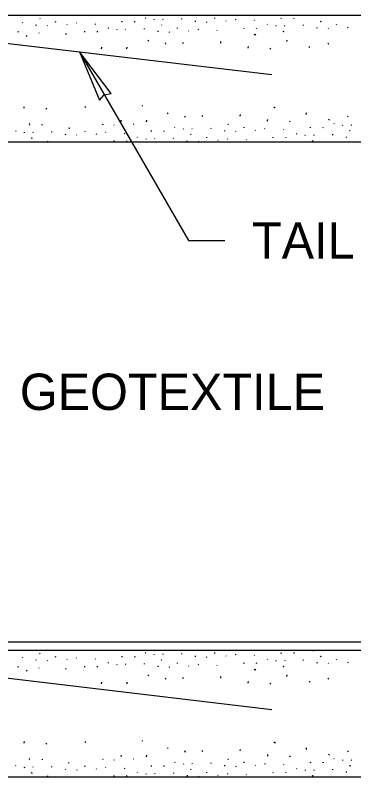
# Model space of a CAD drawing. Extents: x 99862 to 103151, y 100000 to 111076.
# Drawn here: x 100276.5 to 100425.5, y 110543.7 to 110878.5 of the extents above; entities that cross this region are included whole.
import ezdxf

# ---------------------------------------------------------------- set-up
doc = ezdxf.new("R2010")
doc.units = 0
for name, color, linetype in [('Level 11', 7, 'Continuous'), ('Level 15', 7, 'Continuous'), ('Level 18', 7, 'Continuous'), ('Level 20', 7, 'Continuous'), ('Level 24', 7, 'Continuous')]:
    doc.layers.add(name, color=color, linetype=linetype)

msp = doc.modelspace()

# ---------------------------------------------------------------- linework, layer by layer
at = {"layer": 'Level 11'}
for p, q in [((100165.98, 110878.54), (100724.21, 110878.54)), ((100165.98, 110599.43), (100724.21, 110599.43))]:
    msp.add_line(p, q, dxfattribs=at)
at = {"layer": 'Level 15'}
for p, q in [((100304.84, 110862.42), (100352.74, 110779.45)), ((100352.74, 110779.45), (100368.74, 110779.45))]:
    msp.add_line(p, q, dxfattribs=at)
msp.add_lwpolyline([(100304.84, 110862.42), (100313.67, 110841.16), (100315.72, 110843.57), (100318.84, 110844.14)], close=True, dxfattribs=at)
at = {"layer": 'Level 18'}
for p, q in [((100279.78, 110875.19), (100279.83, 110875.54)), ((100285.81, 110874.08), (100285.87, 110874.43)), ((100287.31, 110877.13), (100287.5, 110876.96)), ((100294.33, 110875.52), (100294.38, 110875.86)), ((100299.2, 110874.47), (100299.4, 110874.3)), ((100303.36, 110875.19), (100303.55, 110875.02)), ((100311.65, 110874.8), (100311.84, 110874.63)), ((100323.6, 110875.53), (100323.65, 110875.87)), ((100329.19, 110875.52), (100329.24, 110875.86)), ((100333.77, 110877.46), (100333.96, 110877.29)), ((100337.58, 110876.84), (100337.69, 110876.54)), ((100341.38, 110876.89), (100341.57, 110876.72)), ((100349.81, 110876.78), (100349.87, 110877.13)), ((100355.85, 110875.67), (100355.9, 110876.02)), ((100360.63, 110875.68), (100360.82, 110875.51)), ((100364.36, 110877.11), (100364.42, 110877.45)), ((100369.24, 110876.06), (100369.43, 110875.89)), ((100373.39, 110876.78), (100373.59, 110876.61)), ((100381.68, 110876.38), (100381.87, 110876.22)), ((100387.37, 110874.64), (100387.56, 110874.47)), ((100393.63, 110877.12), (100393.69, 110877.46)), ((100399.22, 110877.11), (100399.28, 110877.45)), ((100410.79, 110875.94), (100410.98, 110875.77)), ((100410.95, 110875.9), (100411.14, 110875.73)), ((100417.96, 110874.29), (100418.02, 110874.64)), ((100277.89, 110871.11), (100277.94, 110871.46)), ((100290.59, 110874.09), (100290.79, 110873.92)), ((100307.16, 110871.12), (100307.22, 110871.47)), ((100312.75, 110871.12), (100312.81, 110871.46)), ((100317.34, 110873.06), (100317.53, 110872.89)), ((100321.14, 110872.44), (100321.26, 110872.14)), ((100324.95, 110872.48), (100325.14, 110872.31)), ((100333.38, 110872.38), (100333.43, 110872.72)), ((100339.41, 110871.27), (100339.47, 110871.61)), ((100340.91, 110874.31), (100341.1, 110874.14)), ((100344.19, 110871.27), (100344.39, 110871.1)), ((100347.93, 110872.7), (100347.98, 110873.05)), ((100352.8, 110871.66), (100353, 110871.49)), ((100356.96, 110872.37), (100357.15, 110872.2)), ((100365.25, 110871.98), (100365.44, 110871.81)), ((100377.2, 110872.71), (100377.25, 110873.06)), ((100382.79, 110872.7), (100382.84, 110873.05)), ((100391.18, 110874.03), (100391.29, 110873.73)), ((100394.35, 110871.54), (100394.55, 110871.37)), ((100394.51, 110871.5), (100394.7, 110871.33)), ((100394.98, 110874.07), (100395.18, 110873.9)), ((100403.41, 110873.96), (100403.47, 110874.31)), ((100409.45, 110872.85), (100409.5, 110873.2)), ((100414.23, 110872.86), (100414.42, 110872.69)), ((100422.84, 110873.24), (100423.03, 110873.07)), ((100281.41, 110869.7), (100281.79, 110869.37)), ((100286.92, 110870.78), (100287.11, 110870.61)), ((100298.63, 110870.47), (100299.01, 110870.13)), ((100381.73, 110870.23), (100382.12, 110869.89)), ((100382.05, 110870.15), (100382.43, 110869.81)), ((100314.55, 110863.78), (100314.65, 110864.47)), ((100325.73, 110863.76), (100325.84, 110864.45)), ((100334.9, 110867.64), (100335.28, 110867.3)), ((100342.51, 110866.41), (100342.74, 110865.81)), ((100350.12, 110866.49), (100350.5, 110866.16)), ((100366.98, 110866.28), (100367.09, 110866.97)), ((100379.05, 110864.06), (100379.15, 110864.75)), ((100396.08, 110866.93), (100396.18, 110867.62)), ((100405.83, 110864.84), (100406.21, 110864.5)), ((100414.14, 110866.27), (100414.52, 110865.93)), ((100388.61, 110864.07), (100388.99, 110863.73)), ((100280.43, 110837.64), (100280.54, 110838.33)), ((100290, 110837.65), (100290.38, 110837.31)), ((100307.22, 110838.42), (100307.6, 110838.08)), ((100332.3, 110838.9), (100332.49, 110838.73)), ((100390.32, 110838.18), (100390.71, 110837.84)), ((100390.64, 110838.09), (100391.02, 110837.76)), ((100343.48, 110835.58), (100343.87, 110835.25)), ((100351.1, 110834.35), (100351.33, 110833.75)), ((100358.71, 110834.44), (100359.09, 110834.1)), ((100375.57, 110834.22), (100375.68, 110834.92)), ((100404.66, 110834.88), (100404.77, 110835.57)), ((100422.73, 110834.22), (100423.11, 110833.88)), ((100282.66, 110831.04), (100282.83, 110830.89)), ((100323.13, 110831.72), (100323.24, 110832.41)), ((100334.32, 110831.7), (100334.43, 110832.39)), ((100387.63, 110832.01), (100387.74, 110832.7)), ((100397.2, 110832.02), (100397.58, 110831.68)), ((100414.42, 110832.78), (100414.8, 110832.45)), ((100416.76, 110830.91), (100416.88, 110830.8)), ((100276.62, 110827.79), (100276.81, 110827.62)), ((100282.88, 110830.26), (100282.93, 110830.61)), ((100288.47, 110830.25), (100288.53, 110830.6)), ((100300.04, 110829.09), (100300.23, 110828.92)), ((100300.2, 110829.05), (100300.39, 110828.88)), ((100307.21, 110827.44), (100307.26, 110827.78)), ((100315.13, 110830.4), (100315.18, 110830.75)), ((100319.91, 110830.41), (100320.1, 110830.24)), ((100328.52, 110830.79), (100328.71, 110830.62)), ((100336.48, 110827.45), (100336.53, 110827.79)), ((100342.07, 110827.44), (100342.13, 110827.78)), ((100346.65, 110829.38), (100346.85, 110829.21)), ((100350.46, 110828.76), (100350.58, 110828.46)), ((100354.27, 110828.81), (100354.46, 110828.64)), ((100362.7, 110828.7), (100362.75, 110829.04)), ((100368.73, 110827.59), (100368.78, 110827.93)), ((100370.07, 110830.67), (100370.26, 110830.51)), ((100370.23, 110830.63), (100370.42, 110830.46)), ((100373.51, 110827.59), (100373.7, 110827.43)), ((100377.24, 110829.02), (100377.3, 110829.37)), ((100382.12, 110827.98), (100382.31, 110827.81)), ((100386.28, 110828.69), (100386.47, 110828.52)), ((100394.56, 110828.3), (100394.76, 110828.13)), ((100406.51, 110829.03), (100406.57, 110829.38)), ((100412.11, 110829.03), (100412.16, 110829.37)), ((100420.5, 110830.35), (100420.61, 110830.05)), ((100423.67, 110827.86), (100423.87, 110827.69)), ((100423.83, 110827.82), (100424.02, 110827.65)), ((100424.3, 110830.39), (100424.49, 110830.22)), ((100280.42, 110827.17), (100280.54, 110826.87)), ((100283.6, 110824.68), (100283.79, 110824.51)), ((100283.76, 110824.64), (100283.95, 110824.47)), ((100284.23, 110827.22), (100284.42, 110827.05)), ((100292.66, 110827.11), (100292.71, 110827.46)), ((100298.69, 110826), (100298.75, 110826.35)), ((100303.48, 110826.01), (100303.67, 110825.84)), ((100312.09, 110826.39), (100312.28, 110826.22)), ((100316.24, 110827.11), (100316.43, 110826.94)), ((100324.53, 110826.71), (100324.72, 110826.55)), ((100330.22, 110824.97), (100330.41, 110824.81)), ((100334.02, 110824.36), (100334.14, 110824.06)), ((100337.83, 110824.4), (100338.02, 110824.23)), ((100346.26, 110824.29), (100346.31, 110824.64)), ((100353.64, 110826.27), (100353.83, 110826.1)), ((100353.8, 110826.23), (100353.99, 110826.06)), ((100360.81, 110824.62), (100360.86, 110824.97)), ((100369.84, 110824.29), (100370.03, 110824.12)), ((100390.08, 110824.63), (100390.13, 110824.98)), ((100395.67, 110824.62), (100395.73, 110824.97)), ((100400.25, 110826.56), (100400.45, 110826.39)), ((100404.06, 110825.95), (100404.18, 110825.65)), ((100407.87, 110825.99), (100408.06, 110825.82)), ((100416.3, 110825.88), (100416.35, 110826.23)), ((100422.33, 110824.77), (100422.38, 110825.12)), ((100290.77, 110823.03), (100290.83, 110823.38)), ((100320.04, 110823.04), (100320.1, 110823.39)), ((100325.64, 110823.03), (100325.69, 110823.38)), ((100352.29, 110823.19), (100352.35, 110823.53)), ((100357.08, 110823.19), (100357.27, 110823.02)), ((100365.69, 110823.57), (100365.88, 110823.41)), ((100378.13, 110823.9), (100378.32, 110823.73)), ((100407.24, 110823.46), (100407.43, 110823.29)), ((100407.4, 110823.41), (100407.59, 110823.24)), ((100287.17, 110598), (100287.36, 110597.84)), ((100287.33, 110597.96), (100287.52, 110597.79)), ((100294.34, 110596.35), (100294.4, 110596.7)), ((100302.26, 110599.32), (100302.28, 110599.43)), ((100307.04, 110599.33), (100307.24, 110599.16)), ((100323.61, 110596.37), (100323.67, 110596.71)), ((100329.2, 110596.36), (100329.26, 110596.7)), ((100333.79, 110598.3), (100333.98, 110598.13)), ((100337.59, 110597.68), (100337.71, 110597.38)), ((100341.4, 110597.72), (100341.59, 110597.56)), ((100349.83, 110597.62), (100349.88, 110597.96)), ((100355.86, 110596.51), (100355.92, 110596.85)), ((100357.39, 110599.43), (100357.4, 110599.42)), ((100357.5, 110599.43), (100357.56, 110599.38)), ((100360.64, 110596.51), (100360.84, 110596.34)), ((100364.38, 110597.94), (100364.43, 110598.29)), ((100369.25, 110596.9), (100369.45, 110596.73)), ((100373.41, 110597.61), (100373.6, 110597.44)), ((100381.7, 110597.22), (100381.89, 110597.05)), ((100393.65, 110597.95), (100393.7, 110598.3)), ((100399.24, 110597.94), (100399.29, 110598.29)), ((100407.63, 110599.27), (100407.74, 110598.97)), ((100410.8, 110596.78), (100411, 110596.61)), ((100410.96, 110596.74), (100411.16, 110596.57)), ((100411.43, 110599.31), (100411.63, 110599.14)), ((100419.86, 110599.2), (100419.9, 110599.43)), ((100279.79, 110596.03), (100279.85, 110596.37)), ((100285.83, 110594.92), (100285.88, 110595.26)), ((100290.61, 110594.92), (100290.8, 110594.76)), ((100299.22, 110595.31), (100299.41, 110595.14)), ((100303.37, 110596.02), (100303.57, 110595.85)), ((100311.66, 110595.63), (100311.85, 110595.46)), ((100317.35, 110593.89), (100317.54, 110593.72)), ((100321.16, 110593.28), (100321.27, 110592.98)), ((100324.96, 110593.32), (100325.16, 110593.15)), ((100333.39, 110593.21), (100333.45, 110593.56)), ((100340.77, 110595.19), (100340.96, 110595.02)), ((100340.93, 110595.15), (100341.12, 110594.98)), ((100347.94, 110593.54), (100348, 110593.88)), ((100356.97, 110593.21), (100357.17, 110593.04)), ((100377.21, 110593.55), (100377.27, 110593.89)), ((100382.8, 110593.54), (100382.86, 110593.89)), ((100387.39, 110595.48), (100387.58, 110595.31)), ((100391.19, 110594.86), (100391.31, 110594.56)), ((100395, 110594.91), (100395.19, 110594.74)), ((100403.43, 110594.8), (100403.48, 110595.15)), ((100409.46, 110593.69), (100409.52, 110594.04)), ((100414.24, 110593.7), (100414.44, 110593.53)), ((100417.98, 110595.13), (100418.03, 110595.47)), ((100422.85, 110594.08), (100423.05, 110593.91)), ((100277.91, 110591.95), (100277.96, 110592.3)), ((100281.42, 110590.54), (100281.81, 110590.2)), ((100286.94, 110591.62), (100287.13, 110591.45)), ((100298.65, 110591.31), (100299.03, 110590.97)), ((100307.18, 110591.96), (100307.23, 110592.31)), ((100312.77, 110591.95), (100312.82, 110592.3)), ((100339.43, 110592.1), (100339.48, 110592.45)), ((100344.21, 110592.11), (100344.4, 110591.94)), ((100352.82, 110592.49), (100353.01, 110592.32)), ((100365.26, 110592.82), (100365.45, 110592.65)), ((100381.75, 110591.07), (100382.13, 110590.73)), ((100382.06, 110590.99), (100382.45, 110590.65)), ((100394.37, 110592.37), (100394.56, 110592.2)), ((100394.53, 110592.33), (100394.72, 110592.16)), ((100334.91, 110588.48), (100335.3, 110588.14)), ((100342.52, 110587.24), (100342.76, 110586.64)), ((100350.13, 110587.33), (100350.52, 110586.99)), ((100366.99, 110587.12), (100367.1, 110587.81)), ((100396.09, 110587.77), (100396.2, 110588.46)), ((100414.15, 110587.11), (100414.54, 110586.77)), ((100314.56, 110584.61), (100314.67, 110585.3)), ((100325.75, 110584.59), (100325.85, 110585.29)), ((100379.06, 110584.9), (100379.17, 110585.59)), ((100388.63, 110584.91), (100389.01, 110584.57)), ((100405.85, 110585.68), (100406.23, 110585.34)), ((100332.31, 110559.73), (100332.5, 110559.56)), ((100280.45, 110558.47), (100280.56, 110559.17)), ((100290.01, 110558.49), (100290.4, 110558.15)), ((100307.23, 110559.25), (100307.62, 110558.91)), ((100343.5, 110556.42), (100343.88, 110556.08)), ((100390.34, 110559.01), (100390.72, 110558.68)), ((100390.65, 110558.93), (100391.04, 110558.59)), ((100404.68, 110555.71), (100404.79, 110556.41)), ((100323.15, 110552.56), (100323.26, 110553.25)), ((100334.33, 110552.54), (100334.44, 110553.23)), ((100351.11, 110555.19), (100351.35, 110554.59)), ((100358.72, 110555.28), (100359.11, 110554.94)), ((100375.58, 110555.06), (100375.69, 110555.75)), ((100387.65, 110552.84), (100387.76, 110553.53)), ((100414.43, 110553.62), (100414.82, 110553.28)), ((100422.74, 110555.05), (100423.13, 110554.71)), ((100282.67, 110551.88), (100282.84, 110551.73)), ((100282.89, 110551.1), (100282.95, 110551.44)), ((100288.49, 110551.09), (100288.54, 110551.44)), ((100300.05, 110549.92), (100300.25, 110549.75)), ((100315.14, 110551.24), (100315.2, 110551.59)), ((100319.93, 110551.25), (100320.12, 110551.08)), ((100328.54, 110551.63), (100328.73, 110551.46)), ((100346.67, 110550.21), (100346.86, 110550.05)), ((100350.48, 110549.6), (100350.59, 110549.3)), ((100354.28, 110549.64), (100354.47, 110549.47)), ((100362.71, 110549.53), (100362.77, 110549.88)), ((100370.09, 110551.51), (100370.28, 110551.34)), ((100370.25, 110551.47), (100370.44, 110551.3)), ((100377.26, 110549.86), (100377.31, 110550.21)), ((100397.21, 110552.85), (100397.6, 110552.52)), ((100406.53, 110549.87), (100406.58, 110550.22)), ((100412.12, 110549.86), (100412.18, 110550.21)), ((100416.77, 110551.74), (100416.9, 110551.63)), ((100420.51, 110551.19), (100420.63, 110550.89)), ((100424.32, 110551.23), (100424.51, 110551.06)), ((100276.63, 110548.63), (100276.83, 110548.46)), ((100280.44, 110548.01), (100280.56, 110547.71)), ((100284.25, 110548.05), (100284.44, 110547.89)), ((100292.68, 110547.95), (100292.73, 110548.29)), ((100298.71, 110546.84), (100298.76, 110547.18)), ((100303.49, 110546.84), (100303.68, 110546.67)), ((100307.22, 110548.27), (100307.28, 110548.62)), ((100312.1, 110547.23), (100312.29, 110547.06)), ((100316.26, 110547.94), (100316.45, 110547.77)), ((100324.54, 110547.55), (100324.74, 110547.38)), ((100336.5, 110548.28), (100336.55, 110548.63)), ((100342.09, 110548.27), (100342.14, 110548.62)), ((100353.65, 110547.11), (100353.85, 110546.94)), ((100353.81, 110547.07), (100354, 110546.9)), ((100368.74, 110548.43), (100368.8, 110548.77)), ((100373.53, 110548.43), (100373.72, 110548.26)), ((100382.14, 110548.81), (100382.33, 110548.65)), ((100386.29, 110549.53), (100386.48, 110549.36)), ((100394.58, 110549.14), (100394.77, 110548.97)), ((100400.27, 110547.4), (100400.46, 110547.23)), ((100404.08, 110546.78), (100404.19, 110546.48)), ((100407.88, 110546.83), (100408.07, 110546.66)), ((100416.31, 110546.72), (100416.37, 110547.06)), ((100423.69, 110548.7), (100423.88, 110548.53)), ((100423.85, 110548.65), (100424.04, 110548.48)), ((100283.62, 110545.52), (100283.81, 110545.35)), ((100283.78, 110545.48), (100283.97, 110545.31)), ((100290.79, 110543.87), (100290.84, 110544.22)), ((100320.06, 110543.88), (100320.11, 110544.23)), ((100325.65, 110543.87), (100325.71, 110544.22)), ((100330.23, 110545.81), (100330.43, 110545.64)), ((100334.04, 110545.19), (100334.16, 110544.89)), ((100337.85, 110545.24), (100338.04, 110545.07)), ((100346.28, 110545.13), (100346.33, 110545.48)), ((100352.31, 110544.02), (100352.36, 110544.37)), ((100357.09, 110544.03), (100357.28, 110543.86)), ((100360.82, 110545.46), (100360.88, 110545.8)), ((100365.7, 110544.41), (100365.89, 110544.24)), ((100369.86, 110545.13), (100370.05, 110544.96)), ((100378.14, 110544.74), (100378.34, 110544.57)), ((100390.1, 110545.47), (100390.15, 110545.81)), ((100395.69, 110545.46), (100395.74, 110545.8)), ((100407.25, 110544.29), (100407.45, 110544.12)), ((100407.41, 110544.25), (100407.6, 110544.08)), ((100422.35, 110545.61), (100422.4, 110545.96))]:
    msp.add_line(p, q, dxfattribs=at)
at = {"layer": 'Level 24'}
for p, q in [((100169.75, 110878.36), (100389.44, 110852.44)), ((100168.04, 110822.82), (100724.21, 110822.9)), ((100174.51, 110603.05), (100724.21, 110603.05)), ((100169.75, 110599.25), (100389.44, 110573.33)), ((100168.04, 110543.71), (100724.21, 110543.78))]:
    msp.add_line(p, q, dxfattribs=at)

# ---------------------------------------------------------------- texts
at = {"layer": 'Level 20'}
for s, p in [('TAIL', (100380.74, 110771.45)), ('GEOTEXTILE', (100278.58, 110704.97))]:
    msp.add_text(s, height=16, dxfattribs=at).set_placement(p)

doc.saveas('drawing.dxf')
